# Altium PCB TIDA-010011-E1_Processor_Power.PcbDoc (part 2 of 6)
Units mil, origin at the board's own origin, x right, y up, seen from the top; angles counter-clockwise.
Board outline 4921.26 x 4921.26 mil, 4 copper layers (Top Layer, Gnd layer, Gnd/Pwr layer, Bottom Layer), stack 62.634 mil thick; 631 components, 254 nets, 1751 pads, 757 vias.
Unrouted connection lines stored in the file: 1.
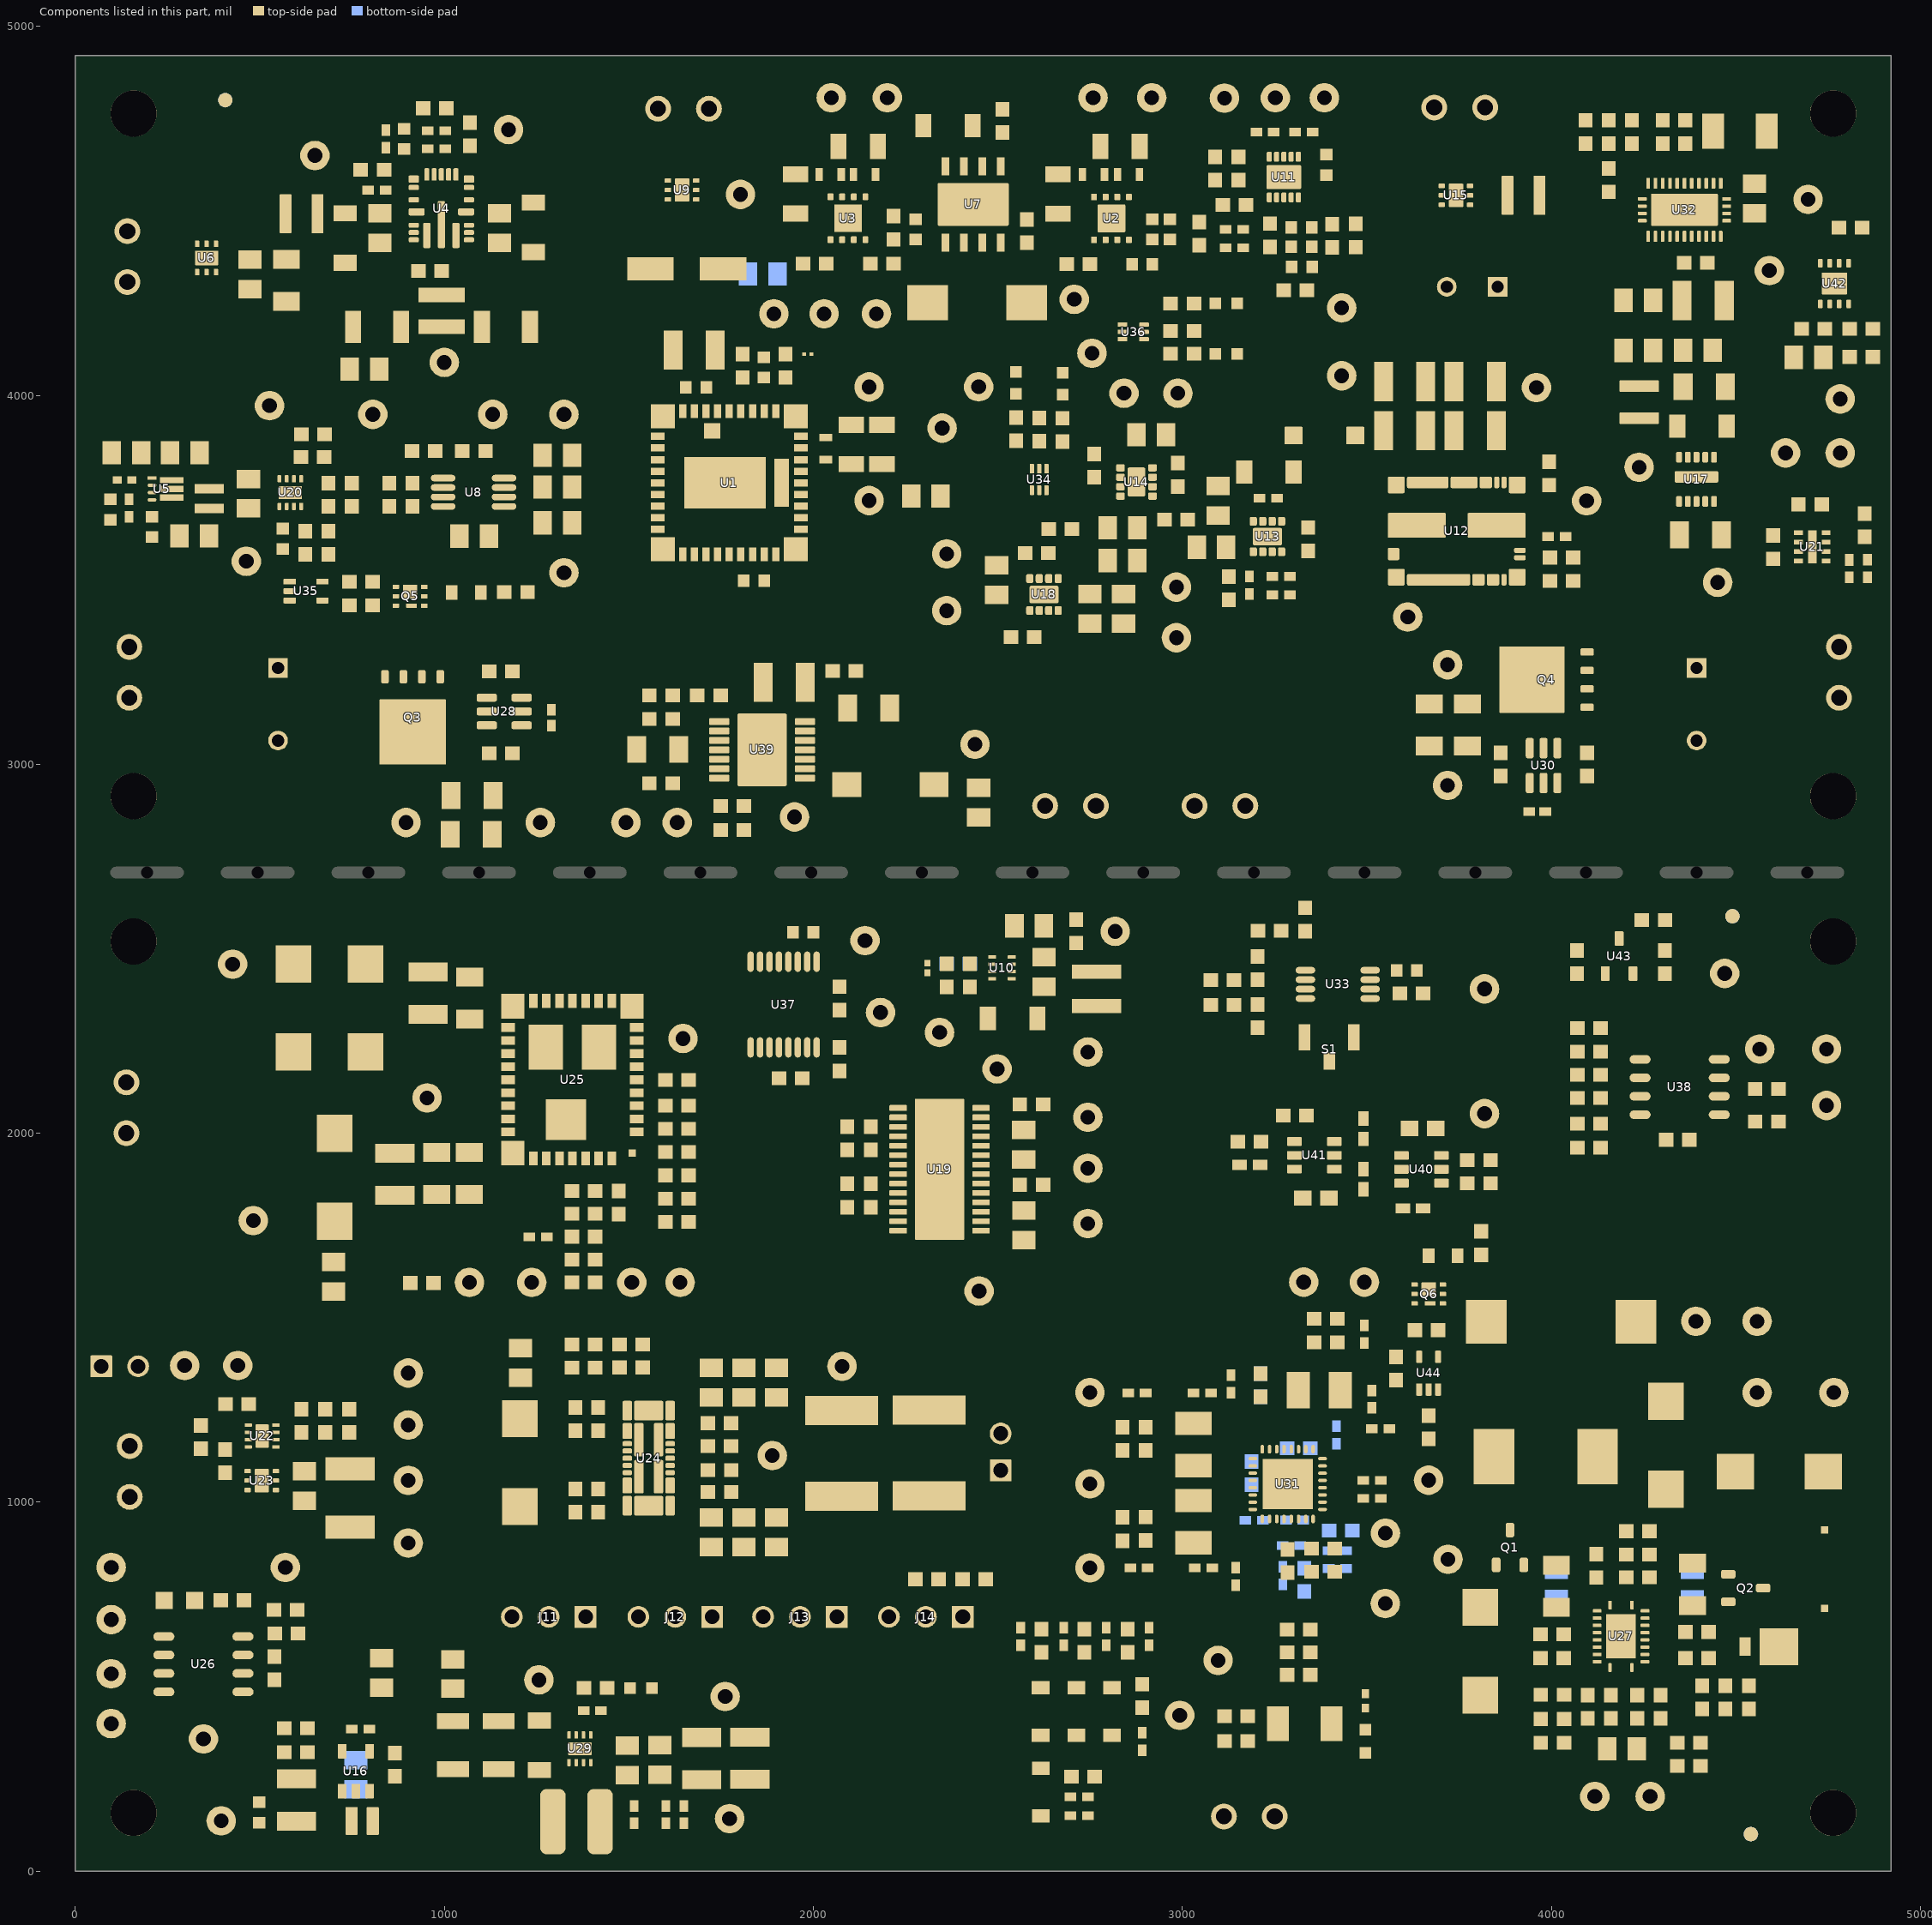
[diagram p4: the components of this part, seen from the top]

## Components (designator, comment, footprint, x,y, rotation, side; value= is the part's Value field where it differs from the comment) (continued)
U17 "LMZM23601V5SILR" SIL0010A 4393.62,3772.22 r270 top
U18 "TPS82085SILR" SIL0008C_SMD 2625.13,3459.94 r90 top
U19 "TPS767D318PWPR" PWP0028D_L 2342,1902 r0 top
U20 "INA381A1DSG" DSG0008A 582.28,3736.26 r90 top
U21 "LMZ10501SIL" SIL0008A 4707.4,3589.2 r180 top
U22 "TPS259531DSGR" DSG0008A 506,1179 r0 top
U23 "TVS1400DRVR" DRV0006A 505,1058.28 r0 top
U24 "TPSM82480MOPR" MOP0024A 1553.73,1118.92 r270 top
U25 "LMZ30604RKGR" RKG0039A 1347.16,2144.93 r180 top
U26 "TPS3705-33DR" D0008A_N 346.81,560.48 r180 top
U27 "TPS75003RHLR" RHL0020A 4189.04,636.15 r180 top
U28 "LM5050-2" tsop-6 1162,3143 r180 top
U29 "TPS62067DSGR" DSG0008A 1367.16,331.4 r90 top
U30 "LM5050-2" tsop-6 3979,2996.43 r90 top
U31 "TPS650250RHBR" RHB0032E 3285.49,1048.84 r0 top
U32 "LM73605RNPR" RNP0030A 4360.91,4502.84 r270 top
U33 "TPS386596L33DGKT" DGK0008A_N 3421.3,2403.31 r0 top
U34 "SN74LVC2G34DRLR" DRL0006A 2612,3772 r90 top
U35 "SN74LVC1G14DCKR" DCK0005A_N 625,3469.26 r0 top
U36 "SN74LVC2G34DRLR" DRL0006A 2867,4171.72 r0 top
U37 "INA250A3PWR" PW0016A_N 1919.44,2348.61 r90 top
U38 "TMP75BIDR" D0008A_N 4348,2125 r180 top
U39 "TPS54325PWPR" PWP0014E_N 1861,3039 r0 top
U40 "TPS27081ADDCR" DDC0006A_N 3648,1902 r180 top
U41 "TPS3808G01DBVR" DBV0006A_N 3358,1940 r180 top
U42 "TPS7A8001ADRBR" DRB0008A 4767.55,4302.92 r90 top
U43 "TMP235DBZ" DBZ0003A_N 4184,2480 r90 top
U44 "SN74LVC1G17DCKR" DCK0005A_N 3667.59,1349.29 r90 top
ZZ1 "This Assembly Note is for PCB labels only" AssemblyNoteLabel 206.81,5575 r0 top
ZZ2 "These assemblies are ESD sensitive, ESD precautions shall be observed." AssemblyNote 206.81,5466.11 r0 top
ZZ3 "These assemblies must be clean and free from flux and all contaminants. Use of no clean flux is not acceptable." AssemblyNote 206.81,5377.56 r0 top
ZZ4 "These assemblies must comply with workmanship standards IPC-A-610 Class 2, unless otherwise specified." AssemblyNote 206.81,5289 r0 top

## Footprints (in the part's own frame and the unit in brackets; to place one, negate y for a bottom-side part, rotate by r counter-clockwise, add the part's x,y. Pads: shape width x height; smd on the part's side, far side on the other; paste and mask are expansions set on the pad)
0201 [mm] "Data from Kemet datasheet CC101_COM dated 7/28/11"
  rect 0.46x0.42 smd mask+0.048: 1(-0.33,0) 2(0.33,0)
  body extent -0.31,-0.16 0.31,0.16, height 0.26
0402#1 [mm] "0402 from SM-752 data"
  rect 0.8x0.6 smd: 1(-0.6,0) 2(0.6,0)
  silkscreen extent -1.22,-0.52 1.22,0.52, body extent -0.55,-0.3 0.55,0.3, height 0.6
0402#2 [mm] "0402 from SM-752 data"
  rect 0.8x0.6 smd: 1(-0.575,-0.013) 2(0.625,-0.013)
  silkscreen extent -1.19,-0.53 1.24,0.51, body extent -0.52,-0.31 0.57,0.29, height 0.6
0402L [mm] "0402 from SM-752 data"
  rect 0.6x0.5 smd: 1(-0.5,0) 2(0.5,0)
  body extent -0.55,-0.3 0.55,0.3, height 0.6
0402M [mm] "0402 from SM-752 data"
  rect 1x0.7 smd: 1(-0.7,0) 2(0.7,0)
  silkscreen extent -1.5,-0.64 1.51,0.65, body extent -0.55,-0.3 0.55,0.3, height 0.6
0603#1 [mm] "0603 from SM-752 data"
  rect 1x0.95 smd: 1(-0.8,0) 2(0.8,0)
  silkscreen extent -1.52,-0.69 1.52,0.69, body extent -0.87,-0.47 0.87,0.47, height 1
0603#2 [mm] "0603 from SM-752 data"
  rect 1x0.95 smd: 1(-0.866,0) 2(0.734,0)
  silkscreen extent -1.52,-0.69 1.52,0.69, body extent -0.87,-0.47 0.87,0.47, height 1
0603L [mm] "0603 from SM-752 data"
  rect 0.8x0.85 smd: 1(-0.7,0) 2(0.7,0)
  silkscreen extent -0.07,-0.33 0.07,0.33, body extent -0.87,-0.47 0.87,0.47, height 1
0603M [mm] "0603 from SM-752 data"
  rect 1.2x1.05 smd: 1(-0.9,0) 2(0.9,0)
  silkscreen extent -1.82,-0.84 1.82,0.84, body extent -0.87,-0.47 0.87,0.47, height 1
0603S [mil]
  rect 20x35 smd: 1(-30,0) 2(30,0)
  silkscreen extent -10,-17 10,17, body extent -34,-19 34,19, height 39
0805_HV [mil] "0805 with 30mil clearance between pads"
  rect 50x63 smd: 1(-40,0) 2(40,0)
  silkscreen extent -74,-40 74,40, body extent -43,-29 43,29, height 57
1206 [mm] "1206 from SM-752 data"
  rect 1.3x1.85 smd: 1(-1.45,0) 2(1.45,0)
  silkscreen extent -2.4,-1.21 2.4,1.21, body extent -1.7,-0.9 1.7,0.9, height 1.35
1206_180 [mm] "1206_180"
  rect 1.1x1.6 smd: 1(-1.7,0) 2(1.7,0)
  silkscreen extent -0.9,-1 0.9,1, body extent -1.75,-0.95 1.75,0.95, height 1.8
1206_190 [mm] "1206_190"
  rect 1.1x1.6 smd: 1(-1.7,0) 2(1.7,0)
  silkscreen extent -0.9,-1 0.9,1, body extent -1.75,-0.95 1.75,0.95, height 1.9
1206L [mm] "1206 from SM-752 data"
  rect 1.1x1.75 smd: 1(-1.35,0) 2(1.35,0)
  silkscreen extent -0.4,-0.77 0.4,0.77, body extent -1.7,-0.9 1.7,0.9, height 1.35
1210 [mm] "1210 from SM-752 data"
  rect 1.3x2.7 smd: 1(-1.45,0) 2(1.45,0)
  silkscreen extent -2.32,-1.57 2.32,1.57, body extent -1.7,-1.35 1.7,1.35, height 1.35
1210_270 [mm] "1210"
  rect 1.3x2.7 smd: 1(-1.45,0) 2(1.45,0)
  silkscreen extent -2.32,-1.57 2.32,1.57, body extent -1.7,-1.35 1.7,1.35, height 2.7
1210_280 [mm] "SMD, 2-Leads, Body 3.6x2.8mm, Height 2.8mm"
  rect 1.1x2.2 smd: 1(-1.65,0) 2(1.65,0)
  silkscreen extent -0.84,-1.4 0.84,1.4, body extent -1.8,-1.4 1.8,1.4, height 2.8
1806_HighSpeed [mm] "Wurth recommended land pattern"
  rrect8% 1.25x1.2 smd: 1(-2.125,0) 2(2.125,0)
  silkscreen extent -1.5,-1 1.5,1, body extent -2.25,-0.8 2.25,0.8, height 1.61
1812_280 [mm] "1812"
  rect 1.6x3.4 smd: 1(-2,0) 2(2,0)
  silkscreen extent -0.8,-1.6 0.8,1.6, body extent -2.4,-1.7 2.4,1.7, height 2.8
7343-20 [mm] "Medium density IPC, based on Kemet case V from T495 datasheet"
  rect 2.55x2.45 smd: 1(-3.025,0) 2(3.025,0)
  silkscreen extent -4.56,-2.3 3.8,2.3, body extent -3.8,-2.3 3.8,2.3, height 2
7343-30 [mm] "Medium Density based on Kemet T495 dimensions"
  rect 2.55x2.45 smd: 1(-3.025,0) 2(3.025,0)
  silkscreen extent -3.8,-2.25 3.8,2.25, body extent -3.8,-2.3 3.8,2.3, height 3.1
7343-43 [mm] "Medium density IPC based on Kemet T495 series"
  rect 2.55x2.45 smd: 1(-3.025,0) 2(3.025,0)
  silkscreen extent -4.56,-2.3 3.8,2.3, body extent -3.8,-2.3 3.8,2.3, height 4.3
AssemblyNote [mil] "Assembly Note"
AssemblyNoteLabel [mil] "Assembly Note for PCB Labels"
B_F_PMSSS4400025PH [mil] "MACHINE SCREW PAN PHILLIPS 4-40"
  round 125 hole 125 unplated mask+5: 1(0,0)
  body extent -109,-109 110,110, height 79
Chemi-Con_1000x2000 [mm] "TH, 2-Leads, Body 10x20mm, Pin Spacing 5mm"
  rect 1.35x1.35 hole 0.85: 1(-2.5,0)
  round 1.35 hole 0.85: 2(2.5,0)
  silkscreen extent -5.25,-5.25 5.25,5.25, body extent -5.25,-5.25 5.25,5.25, height 21.5
CKG57N [mm] "Chip Capacitor, Body 6.0x5.0x5.0mm,"
  rect 2x5 smd: 1(-2.95,0) 2(2.95,0)
  silkscreen extent -3.2,-2.8 3.2,2.8, body extent -3.3,-2.75 3.3,2.75, height 5.5
CONN_1751248 [mil] "Phoenix Contact"
  round 70 hole 43.31: 1(-68.9,0) 2(68.9,0)
  silkscreen extent -148,-142 148,146, body extent -148,-142 148,146, height 335
CONN_PEC02SAAN [mm] "SULLINS"
  rrect7% 1.5x1.5 hole 1.016: 1(-1.27,0)
  round 1.5 hole 1.016: 2(1.27,0)
  silkscreen extent -2.54,-1.52 2.54,1.27, body extent -2.54,-1.27 2.54,1.27, height 8.38
CONN_PEC03SAAN [mm] "SULLINS"
  rect 1.5x1.5 hole 1.016: 1(-2.54,0)
  round 1.5 hole 1.016: 2(0,0) 3(2.54,0)
  silkscreen extent -3.81,-2.06 3.81,1.27, body extent -3.84,-1.3 3.84,1.3, height 8.38
D0008A_N [mm] "SOIC, 8-Leads, Body 4.9x3.9mm, Pitch 1.27mm, IPC Medium Density"
  oval 1.45x0.6 smd: 1(-2.725,1.905) 2(-2.725,0.635) 3(-2.725,-0.635) 4(-2.725,-1.905) 5(2.725,-1.905) 6(2.725,-0.635) 7(2.725,0.635) 8(2.725,1.905)
  silkscreen extent -3.3,-2.5 0.9,2.5, body extent -3,-2.45 3,2.45, height 1.63
DBV0005A_N [mm] "SOT23, 5-Leads, Body 2.9x1.6mm, Pitch 0.95mm, Lead Span 2.8mm, IPC Medium Density"
  rrect17% 1x0.6 smd: 1(-1.375,0.95) 2(-1.375,0) 3(-1.375,-0.95) 4(1.375,-0.95) 5(1.375,0.95)
  silkscreen extent -0.25,-1.55 0.25,1.55, body extent -1.42,-1.46 1.42,1.46, height 1.09
DBV0006A_N [mm] "SOT23, 6-Leads, Body 2.9x1.6mm, Pitch 0.95mm, Lead Span 2.8mm, IPC Medium Density"
  rrect17% 1x0.6 smd: 1(-1.375,0.95) 2(-1.375,0) 3(-1.375,-0.95) 4(1.375,-0.95) 5(1.375,0) 6(1.375,0.95)
  silkscreen extent -1.68,-1.55 0.5,1.55, body extent -1.42,-1.46 1.42,1.46, height 1.12
DBZ0003A_N [mm] "SOT23, 3-Leads, Body 2.9x1.3mm, Pitch 0.95mm, Lead Span 2.4mm, IPC Medium Density"
  rrect17% 1x0.6 smd: 1(-1.2,0.95) 2(-1.2,-0.95) 3(1.2,0)
  silkscreen extent 0.2,-1.5 0.7,1.5, body extent -1.26,-1.46 1.26,1.46, height 0.98
DCK0005A_N [mm] "SOT353, 5-Leads, Body 2x1.3mm, Pitch 0.65mm, Lead Span 2.1mm, IPC Medium Density"
  rrect25% 0.85x0.4 smd: 1(-1.125,0.65) 2(-1.125,0) 3(-1.125,-0.65) 4(1.125,-0.65) 5(1.125,0.65)
  silkscreen extent -1.48,-1.02 0.55,1.1, body extent -1.14,-1 1.14,1, height 0.95
DDA0008A_L [mm] "SOIC, 8-Leads, Body 4.95x3.95mm, Pitch 1.27mm, Thermal Pad 2.29.2x2.29mm, IPC High Density"
  rrect18% 1.25x0.55 smd: 1(-2.625,1.905) 2(-2.625,0.635) 3(-2.625,-0.635) 4(-2.625,-1.905) 5(2.625,-1.905) 6(2.625,-0.635) 7(2.625,0.635) 8(2.625,1.905)
  rrect7% 2.95x4.9 smd paste-1.5 mask-1.5: 9(0,0)
  rrect4% 2.34x2.34 on Top Paste: 9(0,0)
  rrect4% 2.34x2.34 on Top Solder: 9(0,0)
  silkscreen extent -3.47,-2.47 1,2.5, body extent -2.98,-2.45 2.98,2.45, height 1.55
DDC0006A_N [mm]
  rrect17% 1x0.6 smd: 1(-1.375,0.95) 2(-1.375,0) 3(-1.375,-0.95) 4(1.375,-0.95) 5(1.375,0) 6(1.375,0.95)
  silkscreen extent -1.75,-1.52 0.7,1.53, body extent -1.43,-1.48 1.43,1.49, height 0.92
DGK0008A_N [mm] "TSOP, 8-Leads, Body 3x3mm, Pitch 0.65mm, IPC Medium Density"
  oval 1.35x0.45 smd: 1(-2.225,0.975) 2(-2.225,0.325) 3(-2.225,-0.325) 4(-2.225,-0.975) 5(2.225,-0.975) 6(2.225,-0.325) 7(2.225,0.325) 8(2.225,0.975)
  silkscreen extent -2.75,-1.55 0.95,1.55, body extent -2.45,-1.5 2.45,1.5, height 0.96
DLC0008A [mm] "VSON-HR-8"
  rrect40% 0.55x0.25 smd: 1(-0.675,0.75) 2(-0.675,0.25) 3(-0.675,-0.25) 4(-0.675,-0.75) 5(0.675,-0.75) 6(0.675,-0.25) 7(0.675,0.25) 8(0.675,0.75)
  silkscreen extent -0.75,-1.15 0.75,1.15, body extent -0.8,-1.05 0.8,1.05, height 1.02
DQJ0008A [mm] "SMD, 8-Leads, Body 5.75x4.9mm"
  rrect39% 0.91x0.51 smd paste-0.05 mask-0.05: 1(-2.795,1.905) 2(-2.795,0.635) 3(-2.795,-0.635) 4(-2.795,-1.905) 5(2.795,-1.905) 6(2.795,-0.635) 7(2.795,0.635) 8(2.795,1.905)
  rrect8% 1.58x1.25 on Top Paste: 9(-0.38,1.45) 9(-0.38,0) 9(-0.38,-1.45) 9(1.4,1.45) 9(1.4,0) 9(1.4,-1.45)
  rrect3% 3.48x4.47 on Top Solder: 9(0.55,0)
  rrect2% 4.49x4.57 smd paste-2.5 mask-2.5: 9(1.005,0)
  silkscreen extent -3,-2.6 3,2.6, body extent -3.13,-2.45 3.13,2.45, height 1.15
DQK0006C#1 [mm] "WSON"
  rrect12% 0.9x0.86 on Top Paste: 0(0,0.325)
  rrect34% 0.7x0.29 on Top Paste: 0(0.095,-0.65)
  rrect33% 0.45x0.3 smd: 1(-0.975,0.65) 2(-0.975,0) 3(-0.975,-0.65) 4(0.975,-0.65) 5(0.975,0) 6(0.975,0.65)
  rrect33% 0.75x0.3 smd paste-0.15: 7(0.095,-0.65)
  rrect11% 1x0.95 smd paste-0.5: 8(0,0.325)
  silkscreen extent -1.15,-1.15 1.15,1.15, body extent -1,-1 1,1, height 0.82
DQK0006C#2 [mm] "WSON"
  rrect50% 0.9x0.86 on Top Paste: 0(0,0.325)
  rrect50% 0.7x0.29 on Top Paste: 0(0.095,-0.65)
  rrect33% 0.45x0.3 smd: 1(-0.975,0.65) 2(-0.975,0) 3(-0.975,-0.65) 4(0.975,-0.65) 5(0.975,0) 6(0.975,0.65)
  rrect33% 0.75x0.3 smd paste-0.15: 7(0.095,-0.65)
  rrect11% 1x0.95 smd paste-0.5: 8(0,0.325)
  silkscreen extent -1.15,-1.15 1.15,1.15, body extent -1,-1 1,1, height 0.82
DRB0008A [mm] "SON, 8-Leads, Body 3x3mm, Pitch 0.65mm, Thermal Pad 1.75x1.5mm, TI Recommended"
  rrect33% 0.6x0.3 smd: 1(-1.4,0.975) 2(-1.4,0.325) 3(-1.4,-0.325) 4(-1.4,-0.975) 5(1.4,-0.975) 6(1.4,-0.325) 7(1.4,0.325) 8(1.4,0.975)
  rrect7% 1.5x1.75 smd paste-0.75: 9(0,0)
  Top Layer region: -0.465,-1.5 -0.465,-0.875 -0.75,-0.875 -0.75,0.875 -0.465,0.875 -0.465,1.5 -0.185,1.5 -0.185,0.875 0.185,0.875 0.185,1.5 0.465,1.5 0.465,0.875 0.75,0.875 0.75,-0.875 0.465,-0.875 0.465,-1.5 0.185,-1.5 0.185,-0.875 -0.185,-0.875 -0.185,-1.5
  silkscreen extent -1.73,-1.73 1.73,1.73, body extent -1.58,-1.57 1.57,1.58, height 1.01
DRC0010J [mm] "SON, 10-Leads, Body 3x3mm, Pitch 0.5mm, Thermal Pad 2.4x1.65mm, TI Recommended"
  rrect57% 0.7x0.35 smd paste-0.05 mask-0.05: 1(-1.4,1) 2(-1.4,0.5) 3(-1.4,0) 4(-1.4,-0.5) 5(-1.4,-1) 6(1.4,-1) 7(1.4,-0.5) 8(1.4,0) 9(1.4,0.5) 10(1.4,1)
  rrect40% 0.25x0.34 on Top Paste: 11(-0.25,1.53) 11(-0.25,-1.53) 11(0.25,1.53) 11(0.25,-1.53)
  rrect9% 1.5x1.06 on Top Paste: 11(0,0.63) 11(0,-0.63)
  rrect12% 1.65x2.4 smd paste-1 mask-2: 11(0,0)
  Top Layer region: -0.25,1.1 0.25,1.1 0.25,1.75 -0.25,1.75
  Top Layer region: -0.25,-1.75 0.25,-1.75 0.25,-1.1 -0.25,-1.1
  Top Layer region: -0.775,-1.25 -0.425,-1.25 -0.425,-1.65 -0.417,-1.688 -0.396,-1.721 -0.363,-1.742 -0.325,-1.75 -0.325,-1.75 -0.325,-1.75 -0.175,-1.75 -0.175,-1.75 -0.137,-1.742 -0.104,-1.721 -0.083,-1.688 -0.075,-1.65 -0.075,-1.65 -0.075,-1.25 0.075,-1.25 0.075,-1.65 0.083,-1.688 0.104,-1.721 0.137,-1.742 0.175,-1.75 0.175,-1.75 0.175,-1.75 0.325,-1.75 0.325,-1.75 0.363,-1.742 0.396,-1.721 0.417,-1.688 0.425,-1.65 0.425,-1.65 0.425,-1.25 0.775,-1.25 0.813,-1.242 0.846,-1.221 0.867,-1.188 0.875,-1.15 0.875,-1.15 0.875,1.15 0.867,1.188 0.846,1.221 0.813,1.242 0.775,1.25 0.775,1.25 0.425,1.25 0.425,1.65 0.417,1.688 0.396,1.721 0.363,1.742 0.325,1.75 0.325,1.75 0.175,1.75 0.137,1.742 0.104,1.721 0.083,1.688 0.075,1.65 0.075,1.65 0.075,1.25 -0.075,1.25 -0.075,1.65 -0.083,1.688 -0.104,1.721 -0.137,1.742 -0.175,1.75 -0.175,1.75 -0.325,1.75 -0.363,1.742 -0.396,1.721 -0.417,1.688 -0.425,1.65 -0.425,1.65 -0.425,1.25 -0.775,1.25 -0.813,1.242 -0.846,1.221 -0.867,1.188 -0.875,1.15 -0.875,1.15 -0.875,-1.15 -0.867,-1.188 -0.846,-1.221 -0.813,-1.242 -0.775,-1.25
  silkscreen extent -1.63,-1.63 1.63,1.63, body extent -1.5,-1.5 1.5,1.5, height 0.77
DRL0006A [mm] "SOTFL, 6-Flat Leads, Body 1.2x1.6x0.6mm, Pitch 0.5mm, TI recommended"
  rrect33% 0.67x0.3 smd: 1(-0.74,0.5) 2(-0.74,0) 3(-0.74,-0.5) 4(0.74,-0.5) 5(0.74,0) 6(0.74,0.5)
  silkscreen extent -0.9,-0.95 0.5,0.95, body extent -0.8,-0.8 0.8,0.8, height 0.61
DRV0006A [mm] "SON, 6-Leads, Body 2x2mm, Pitch 0.65mm, Thermal Pad 1.6x1mm, TI Recommended"
  rrect33% 0.45x0.3 smd: 1(-0.975,0.65) 2(-0.975,0) 3(-0.975,-0.65) 4(0.975,-0.65) 5(0.975,0) 6(0.975,0.65)
  rrect14% 1x0.7 on Top Paste: 7(0,0.45) 7(0,-0.45)
  rrect10% 1x1.6 smd paste-0.5: 7(0,0)
  silkscreen extent -1.05,-1.2 1.05,1.2, body extent -1.05,-1.05 1.05,1.05, height 0.81
DSG0008A [mm] "SON, 8-Leads, Body 2x2mm, Pitch 0.5mm, Thermal Pad 1.6x0.9mm, TI Recommended"
  rrect40% 0.5x0.25 smd: 1(-0.95,0.75) 2(-0.95,0.25) 3(-0.95,-0.25) 4(-0.95,-0.75) 5(0.95,-0.75) 6(0.95,-0.25) 7(0.95,0.25) 8(0.95,0.75)
  rrect14% 0.9x0.7 on Top Paste: 9(0,0.45) 9(0,-0.45)
  rrect11% 0.9x1.6 smd paste-0.45: 9(0,0)
  silkscreen extent -1.07,-1.15 1.07,1.15, body extent -1,-1 1,1, height 0.77
ESD_Overlay_Medium [mil]
  silkscreen extent -127,-109 125,110
FCC_disclaimer_stacked [mil]
Fiducial10-30 [mm]
  round 1 smd mask+1: 1(0,0)
  Top Layer keep-out circle w1.678: c0,0 r0.75
GX_2TERM [mm] "PANASONIC"
  rect 2.8x2.4 smd: 1(-3.4,0) 2(3.4,0)
  silkscreen extent -4.45,-2.4 3.8,2.4, body extent -3.75,-2.25 3.75,2.25, height 2.01
IND_WE-LHMI-4020 [mm] "WERTH"
  rect 1.5x2.4 smd: 1(-1.85,0) 2(1.85,0)
  silkscreen extent -2.2,-2.2 2.2,2.2, body extent -2.15,-2.15 2.15,2.15, height 2
Keystone5000 [mil] "For Keystone 500x miniature loop terminals"
  round 80 hole 40: 1(0,0)
  silkscreen extent -52,-52 52,52, body extent -49,-49 49,49, height 182
Keystone5001 [mil] "For Keystone 500x miniature loop terminals"
  round 80 hole 40: 1(0,0)
  silkscreen extent -52,-52 52,52, body extent -49,-49 49,49, height 182
Keystone5002 [mil] "For Keystone 500x miniature loop terminals"
  round 80 hole 40: 1(0,0)
  silkscreen extent -52,-52 52,52, body extent -49,-49 49,49, height 182
Keystone5003 [mil] "For Keystone 500x miniature loop terminals"
  round 80 hole 40: 1(0,0)
  silkscreen extent -52,-52 52,52, body extent -49,-49 49,49, height 182
Keystone_1902E [mil] "Hex Standoff, 4-40 threaded, nylon"
  round 1 on Mech4: 0(0,0)
  body extent -145,-126 146,126, height 1001
KZN_800x1500 [mm] "TH, 2-Leads, Dia 8mm, Pin Spacing 3.5mm"
  rect 1.35x1.35 hole 0.85: 1(-1.75,0)
  round 1.35 hole 0.85: 2(1.75,0)
  silkscreen extent -4.25,-4.25 4.25,4.25, body extent -4.22,-4.24 4.24,4.24, height 16.51
Label_650x200 [mil] "Thermal Transfer Label"
  round 1 on Mech13: 0(0,0)
  silkscreen extent -325,-100 325,100, body extent -325,-100 325,100, height 1
LED_LTST-C170_Red [mm] "LITE-ON"
  rect 1.2x1.2 smd: 1(-1.05,0) 2(1.05,0)
  silkscreen extent -1.6,-1 2.2,1, body extent -1.05,-0.67 1.05,0.67, height 1.1
LED_LTST-C190_G [mm] "Lite-On"
  rect 0.8x0.8 smd: 1(-0.75,0) 2(0.75,0)
  silkscreen extent 1.38,-0.5 1.75,0.5, body extent -0.85,-0.45 0.85,0.45, height 0.9
LG_M67K_Green [mm] "SMD, 2-Leads, Body 2x1.4mm, Pitch 2mm"
  rect 0.8x1 smd mask+0: 1(-1,0) 2(1,0)
  silkscreen extent -2.1,-1 1.05,1, body extent -1.05,-0.75 1.05,0.75, height 1.4
MOP0024A [mm] "QFM, 24-Leads, Body 3.6x7.9mm"
  rrect31% 1.35x0.65 smd paste-1 mask-0.05: 1(-3.275,1.475) 3(-3.275,-1.475) 11(3.275,-1.475) 13(3.275,1.475)
  rrect19% 1.17x0.52 on Top Paste: 1(3.275,1.475) 9(-3.275,1.475) 11(-3.275,-1.475) 19(3.275,-1.475)
  rrect15% 1.35x2 smd paste-1 mask-0.05: 2(-3.275,0) 12(3.275,0)
  rrect19% 0.95x0.52 on Top Paste: 2(1.875,1.475) 8(-1.875,1.475) 12(-1.875,-1.475) 18(1.875,-1.475)
  rrect31% 1.1x0.65 smd paste-1 mask-0.05: 4(-1.875,-1.475) 10(1.875,-1.475) 14(1.875,1.475) 20(-1.875,1.475)
  rrect57% 0.35x0.65 smd paste-0.05 mask-0.05: 5(-1,-1.475) 6(-0.5,-1.475) 7(0,-1.475) 8(0.5,-1.475) 9(1,-1.475) 15(1,1.475) 16(0.5,1.475) 17(0,1.475) 18(-0.5,1.475) 19(-1,1.475)
  rrect9% 1.17x1.7 on Top Paste: 10(-3.275,0) 20(3.275,0)
  rrect31% 2.3x0.65 smd paste-1 mask-0.05: 21(-1.275,0.675) 22(1.275,0.675) 23(1.275,-0.675) 24(-1.275,-0.675)
  rrect19% 0.98x0.52 on Top Paste: 21(0.685,0.675) 21(1.865,0.675) 22(-1.865,0.675) 22(-0.685,0.675) 23(-1.865,-0.675) 23(-0.685,-0.675) 24(0.685,-0.675) 24(1.865,-0.675)
  Top Layer region: -3.85,1 -3.888,0.992 -3.921,0.971 -3.942,0.938 -3.95,0.9 -3.95,0.9 -3.95,-1.7 -3.942,-1.738 -3.921,-1.771 -3.888,-1.792 -3.85,-1.8 -3.85,-1.8 -2.7,-1.8 -2.662,-1.792 -2.629,-1.771 -2.608,-1.738 -2.6,-1.7 -2.6,-1.7 -2.6,-0.025 -2.6,-0.025 -2.592,0.013 -2.571,0.046 -2.538,0.067 -2.5,0.075 -2.5,0.075 -0.225,0.075 -0.187,0.083 -0.154,0.104 -0.133,0.137 -0.125,0.175 -0.125,0.175 -0.125,0.9 -0.133,0.938 -0.154,0.971 -0.187,0.992 -0.225,1 -0.225,1 -1.225,1 -1.263,1.008 -1.296,1.029 -1.317,1.062 -1.325,1.1 -1.325,1.1 -1.325,1.7 -1.333,1.738 -1.354,1.771 -1.387,1.792 -1.425,1.8 -1.425,1.8 -2.325,1.8 -2.363,1.792 -2.396,1.771 -2.417,1.738 -2.425,1.7 -2.425,1.7 -2.425,1.1 -2.433,1.062 -2.454,1.029 -2.487,1.008 -2.525,1 -2.525,1
  Top Layer region: 3.85,1 3.888,0.992 3.921,0.971 3.942,0.938 3.95,0.9 3.95,0.9 3.95,-1.7 3.942,-1.738 3.921,-1.771 3.888,-1.792 3.85,-1.8 3.85,-1.8 2.7,-1.8 2.662,-1.792 2.629,-1.771 2.608,-1.738 2.6,-1.7 2.6,-1.7 2.6,-0.025 2.6,-0.025 2.592,0.013 2.571,0.046 2.538,0.067 2.5,0.075 2.5,0.075 0.225,0.075 0.187,0.083 0.154,0.104 0.133,0.137 0.125,0.175 0.125,0.175 0.125,0.9 0.133,0.938 0.154,0.971 0.187,0.992 0.225,1 0.225,1 1.225,1 1.263,1.008 1.296,1.029 1.317,1.062 1.325,1.1 1.325,1.1 1.325,1.7 1.333,1.738 1.354,1.771 1.387,1.792 1.425,1.8 1.425,1.8 2.325,1.8 2.363,1.792 2.396,1.771 2.417,1.738 2.425,1.7 2.425,1.7 2.425,1.1 2.433,1.062 2.454,1.029 2.487,1.008 2.525,1 2.525,1
  Top Layer region: -2.325,-1.8 -2.363,-1.792 -2.396,-1.771 -2.417,-1.738 -2.425,-1.7 -2.425,-1.7 -2.425,-0.175 -2.417,-0.137 -2.396,-0.104 -2.363,-0.083 -2.325,-0.075 -2.325,-0.075 -0.225,-0.075 -0.187,-0.083 -0.154,-0.104 -0.133,-0.137 -0.125,-0.175 -0.125,-0.175 -0.125,-0.9 -0.133,-0.938 -0.154,-0.971 -0.187,-0.992 -0.225,-1 -0.225,-1 -1.225,-1 -1.263,-1.008 -1.296,-1.029 -1.317,-1.062 -1.325,-1.1 -1.325,-1.1 -1.325,-1.7 -1.333,-1.738 -1.354,-1.771 -1.387,-1.792 -1.425,-1.8 -1.425,-1.8
  Top Layer region: 2.325,-1.8 2.363,-1.792 2.396,-1.771 2.417,-1.738 2.425,-1.7 2.425,-1.7 2.425,-0.175 2.417,-0.137 2.396,-0.104 2.363,-0.083 2.325,-0.075 2.325,-0.075 0.225,-0.075 0.187,-0.083 0.154,-0.104 0.133,-0.137 0.125,-0.175 0.125,-0.175 0.125,-0.9 0.133,-0.938 0.154,-0.971 0.187,-0.992 0.225,-1 0.225,-1 1.225,-1 1.263,-1.008 1.296,-1.029 1.317,-1.062 1.325,-1.1 1.325,-1.1 1.325,-1.7 1.333,-1.738 1.354,-1.771 1.387,-1.792 1.425,-1.8 1.425,-1.8
  silkscreen extent -4.15,-2 4.15,2, body extent -4,-1.85 4,1.85, height 1.55
MUA08A_N [mm] "TSOP, 8-Leads, Body 3x3mm, Pitch 0.65mm, IPC Medium Density"
  oval 1.7x0.45 smd: 1(-2.1,0.975) 2(-2.1,0.325) 3(-2.1,-0.325) 4(-2.1,-0.975) 5(2.1,-0.975) 6(2.1,-0.325) 7(2.1,0.325) 8(2.1,0.975)
  silkscreen extent -2.22,-1.55 0.85,1.87, body extent -1.6,-1.6 1.6,1.6, height 1.09
Net-Tie_10mil [mil] "10mil net tie, no solder mask opening, no solder paste"
  rect 10x10 smd paste-5 mask-5: 1(-10,0) 2(10,0)
  Top Layer region: -6,5 6,5 6,-5 -6,-5
NR3015 [mm] "SMD, 2-Leads, Body 3x3mm"
  rrect12% 0.8x2.7 smd: 1(-1.1,0) 2(1.1,0)
  silkscreen extent -0.3,-1.6 0.3,1.6, body extent -1.5,-1.5 1.5,1.5, height 1.5
Pb-Free_Overlay_Small [mil]
  silkscreen extent -46,-46 46,46
POWERMITE [mil] "On Semi recommended land pattern, 457-04.pdf Rev 04E dated 2008-11-26"
  rect 105x100 smd: 1(-46,0)
  rect 30x50 smd: 2(46,0)
  silkscreen extent -124,-63 61,63, body extent -94,-40 59,40, height 45
PW0016A_N [mm] "TSOP, 16-Leads, Body 5x4.4mm, Pitch 0.65mm, IPC Medium Density"
  oval 1.4x0.45 smd: 1(-2.95,2.275) 2(-2.95,1.625) 3(-2.95,0.975) 4(-2.95,0.325) 5(-2.95,-0.325) 6(-2.95,-0.975) 7(-2.95,-1.625) 8(-2.95,-2.275) 9(2.95,-2.275) 10(2.95,-1.625) 11(2.95,-0.975) 12(2.95,-0.325) 13(2.95,0.325) 14(2.95,0.975) 15(2.95,1.625) 16(2.95,2.275)
  silkscreen extent -3.5,-2.55 1.85,2.75, body extent -3.21,-2.5 3.21,2.5, height 1
PWP0014E_N [mm] "TSOP, 14-Leads, Body 5x4.4mm, Pitch 0.65mm, Thermal Pad 3x3 mm, IPC Medium Density"
  rrect22% 1.4x0.45 smd: 1(-2.95,1.95) 2(-2.95,1.3) 3(-2.95,0.65) 4(-2.95,0) 5(-2.95,-0.65) 6(-2.95,-1.3) 7(-2.95,-1.95) 8(2.95,-1.95) 9(2.95,-1.3) 10(2.95,-0.65) 11(2.95,0) 12(2.95,0.65) 13(2.95,1.3) 14(2.95,1.95)
  rrect6% 3.4x5 smd paste-2 mask-2: 15(0,0)
  rrect4% 2.46x2.31 on Top Paste: 15(0,0)
  rrect4% 2.46x2.31 on Top Solder: 15(0,0)
  silkscreen extent -3.47,-2.65 1.7,2.65, body extent -3.21,-2.5 3.21,2.5, height 1
PWP0028D_L [mm] "TSOP, 28-Leads, Body 9.7x4.4mm, Pitch 0.65mm, Exposed Pad, IPC High Density"
  rrect25% 1.2x0.4 smd: 1(-2.85,4.225) 2(-2.85,3.575) 3(-2.85,2.925) 4(-2.85,2.275) 5(-2.85,1.625) 6(-2.85,0.975) 7(-2.85,0.325) 8(-2.85,-0.325) 9(-2.85,-0.975) 10(-2.85,-1.625) 11(-2.85,-2.275) 12(-2.85,-2.925) 13(-2.85,-3.575) 14(-2.85,-4.225) 15(2.85,-4.225) 16(2.85,-3.575) 17(2.85,-2.925) 18(2.85,-2.275) 19(2.85,-1.625) 20(2.85,-0.975) 21(2.85,-0.325) 22(2.85,0.325) 23(2.85,0.975) 24(2.85,1.625) 25(2.85,2.275) 26(2.85,2.925) 27(2.85,3.575) 28(2.85,4.225)
  rrect3% 3.4x9.7 smd paste-1.7 mask-1.7: 29(0,0)
  rrect4% 2.4x6.46 on Top Paste: 29(0,0)
  rrect4% 2.4x6.46 on Top Solder: 29(0,0)
  silkscreen extent -3.5,-4.9 2,4.9, body extent -3.21,-4.85 3.21,4.85, height 1
RHB0032E [mm] "QFN, 32-Leads, Body 5x5mm, Pitch 0.5mm, Thermal Pad 3.45x3.45mm, TI Recommended"
  oval 0.6x0.24 smd: 1(-2.4,1.75) 2(-2.4,1.25) 3(-2.4,0.75) 4(-2.4,0.25) 5(-2.4,-0.25) 6(-2.4,-0.75) 7(-2.4,-1.25) 8(-2.4,-1.75) 17(2.4,-1.75) 18(2.4,-1.25) 19(2.4,-0.75) 20(2.4,-0.25) 21(2.4,0.25) 22(2.4,0.75) 23(2.4,1.25) 24(2.4,1.75)
  oval 0.24x0.6 smd: 9(-1.75,-2.4) 10(-1.25,-2.4) 11(-0.75,-2.4) 12(-0.25,-2.4) 13(0.25,-2.4) 14(0.75,-2.4) 15(1.25,-2.4) 16(1.75,-2.4) 25(1.75,2.4) 26(1.25,2.4) 27(0.75,2.4) 28(0.25,2.4) 29(-0.25,2.4) 30(-0.75,2.4) 31(-1.25,2.4) 32(-1.75,2.4)
  rect 3.45x3.45 smd paste-1.725: 33(0,0)
  silkscreen extent -2.72,-2.73 2.72,2.73, body extent -2.57,-2.57 2.58,2.58, height 1.01
RHL0020A [mm] "QFN, 20-Leads, Body 4.5x3.5mm, Pitch 0.5mm, Thermal Pad 3.05x2.05mm, TI Recommended"
  rrect42% 0.24x0.6 smd: 1(-0.75,2.15) 10(-0.75,-2.15) 11(0.75,-2.15) 20(0.75,2.15)
  rrect42% 0.6x0.24 smd: 2(-1.65,1.75) 3(-1.65,1.25) 4(-1.65,0.75) 5(-1.65,0.25) 6(-1.65,-0.25) 7(-1.65,-0.75) 8(-1.65,-1.25) 9(-1.65,-1.75) 12(1.65,-1.75) 13(1.65,-1.25) 14(1.65,-0.75) 15(1.65,-0.25) 16(1.65,0.25) 17(1.65,0.75) 18(1.65,1.25) 19(1.65,1.75)
  rrect12% 0.92x0.85 on Top Paste: 21(-0.56,1.05) 21(-0.56,0) 21(-0.56,-1.05) 21(0.56,1.05) 21(0.56,0) 21(0.56,-1.05)
  rrect5% 2.05x3.05 smd paste-2 mask+0: 21(0,0)
  Top Layer region: -0.975,-1.575 -0.425,-1.575 -0.425,-2.4 -0.417,-2.438 -0.396,-2.471 -0.363,-2.492 -0.325,-2.5 -0.325,-2.5 -0.225,-2.5 -0.187,-2.492 -0.154,-2.471 -0.133,-2.438 -0.125,-2.4 -0.125,-2.4 -0.125,-1.975 0.125,-1.975 0.125,-2.4 0.133,-2.438 0.154,-2.471 0.187,-2.492 0.225,-2.5 0.225,-2.5 0.325,-2.5 0.363,-2.492 0.396,-2.471 0.417,-2.438 0.425,-2.4 0.425,-2.4 0.425,-1.575 0.975,-1.575 1.013,-1.567 1.046,-1.546 1.067,-1.513 1.075,-1.475 1.075,-1.475 1.075,1.475 1.067,1.513 1.046,1.546 1.013,1.567 0.975,1.575 0.975,1.575 0.425,1.575 0.425,2.4 0.417,2.438 0.396,2.471 0.363,2.492 0.325,2.5 0.325,2.5 0.225,2.5 0.187,2.492 0.154,2.471 0.133,2.438 0.125,2.4 0.125,2.4 0.125,1.975 -0.125,1.975 -0.125,2.4 -0.133,2.438 -0.154,2.471 -0.187,2.492 -0.225,2.5 -0.225,2.5 -0.325,2.5 -0.363,2.492 -0.396,2.471 -0.417,2.438 -0.425,2.4 -0.425,2.4 -0.425,1.575 -0.975,1.575 -1.013,1.567 -1.046,1.546 -1.067,1.513 -1.075,1.475 -1.075,1.475 -1.075,-1.475 -1.067,-1.513 -1.046,-1.546 -1.013,-1.567 -0.975,-1.575
  silkscreen extent -1.98,-2.47 1.98,2.47, body extent -1.75,-2.25 1.75,2.25, height 1.01
RKG0039A [mm]
  rect 0.5x0.5 smd paste-0.25: 1(-4.1,5.05)
  rect 0.95x0.6 smd paste-0.025: 2(-4.425,3.6) 3(-4.425,2.7) 4(-4.425,1.8) 5(-4.425,0.9) 6(-4.425,0) 7(-4.425,-0.9) 8(-4.425,-1.8) 9(-4.425,-2.7) 10(-4.425,-3.6) 20(4.425,-3.6) 21(4.425,-2.7) 22(4.425,-1.8) 23(4.425,-0.9) 24(4.425,0) 25(4.425,0.9) 26(4.425,1.8) 27(4.425,2.7) 28(4.425,3.6)
  rect 1.6x1.7 smd paste-0.8: 11(-4.1,-5.05) 19(4.1,-5.05) 29(4.1,5.05)
  rect 0.6x0.95 smd paste-0.025: 12(-2.7,-5.425) 13(-1.8,-5.425) 14(-0.9,-5.425) 15(0,-5.425) 16(0.9,-5.425) 17(1.8,-5.425) 18(2.7,-5.425) 30(2.7,5.425) 31(1.8,5.425) 32(0.9,5.425) 33(0,5.425) 34(-0.9,5.425) 35(-1.8,5.425) 36(-2.7,5.425)
  rect 2.8x2.8 smd paste-1.387 mask-0.6: 37(0.45,2.75)
  rect 2.35x3.1 smd paste-1.537: 38(-1.83,-2.25) 39(1.84,-2.25)
  Top Layer region: -4.9,5.9 -3.3,5.9 -3.3,4.8 -3.9,4.2 -4.9,4.2
  silkscreen extent -5.15,-6.15 5.15,6.15, body extent -4.57,-5.57 4.57,5.57, height 2.91
RLR0018A [mm] "B2QFN, Body 7x9mm"
  rrect17% 1.15x1.17 smd paste-1.15 mask-1.15: 1(-3.175,4.165) 7(-3.175,-4.165) 10(3.175,-4.165) 15(3.175,4.165)
  rrect57% 0.8x0.35 smd paste-0.05 mask-0.05: 2(-3.35,3.25) 3(-3.35,2.75) 14(3.35,3.25)
  rrect25% 0.8x0.85 smd paste-0.4 mask-0.4: 4(-3.35,2) 12(3.35,1.5) 13(3.35,2.5)
  rrect25% 0.8x1.85 smd paste-0.4 mask-0.4: 5(-3.35,0.5)
  rrect25% 0.8x2.85 smd paste-0.4 mask-0.4: 6(-3.35,-2)
  rrect40% 0.25x0.5 on Top Solder: 8(-0.895,-4.45) 8(-0.395,-4.45) 8(0.105,-4.45) 18(-0.895,4.45) 18(-0.395,4.45) 18(0.105,4.45)
  rrect6% 1.6x3.48 on Top Solder: 8(-0.395,-2.521) 18(-0.395,2.519)
  rrect8% 1.7x4.005 smd paste-2 mask-2: 8(-0.395,-2.748) 18(-0.395,2.748)
  rrect25% 0.85x0.8 smd paste-0.4 mask-0.4: 9(1.58,-4.35)
  rrect25% 0.8x4.35 smd paste-0.4 mask-0.4: 11(3.35,-1.25)
  rrect57% 0.35x0.8 smd paste-0.05 mask-0.05: 16(1.83,4.35) 17(1.33,4.35)
  rrect40% 0.265x0.25 on Top Paste: ""(-3.568,3.75) ""(-3.568,-3.75) ""(3.568,3.75) ""(3.568,-3.75)
  rrect17% 0.585x0.61 on Top Paste: ""(-2.943,3.93) ""(-2.943,-3.93) ""(2.943,3.93) ""(2.943,-3.93)
  rrect40% 0.25x0.265 on Top Paste: ""(-2.775,4.568) ""(-2.775,-4.568) ""(-0.895,4.568) ""(-0.895,-4.568) ""(-0.395,4.568) ""(-0.395,-4.568) ""(0.105,4.568) ""(0.105,-4.568) ""(2.775,4.568) ""(2.775,-4.568)
  rrect15% 0.67x0.71 on Top Paste: ""(-0.83,3.9) ""(-0.83,2.99) ""(-0.83,2.08) ""(-0.83,1.17) ""(-0.83,-1.17) ""(-0.83,-2.08) ""(-0.83,-2.99) ""(-0.83,-3.9) ""(0.04,3.9) ""(0.04,2.99) ""(0.04,2.08) ""(0.04,1.17) ""(0.04,-1.17) ""(0.04,-2.08) ""(0.04,-2.99) ""(0.04,-3.9)
  Top Layer region: -3.7,-4.75 -3.719,-4.746 -3.735,-4.735 -3.746,-4.719 -3.75,-4.7 -3.75,-4.7 -3.75,-0.675 -3.742,-0.637 -3.721,-0.604 -3.688,-0.583 -3.65,-0.575 -3.65,-0.575 0.71,-0.575 0.729,-0.579 0.745,-0.59 0.756,-0.606 0.76,-0.625 0.76,-0.625 0.76,-4.7 0.756,-4.719 0.745,-4.735 0.729,-4.746 0.71,-4.75 0.71,-4.75
  Top Layer region: -3.65,-0.425 -3.688,-0.417 -3.721,-0.396 -3.742,-0.363 -3.75,-0.325 -3.75,-0.325 -3.75,1.325 -3.742,1.363 -3.721,1.396 -3.688,1.417 -3.65,1.425 -3.65,1.425 -2.5,1.425 -2.481,1.429 -2.465,1.44 -2.454,1.456 -2.45,1.475 -2.45,1.475 -2.45,4.7 -2.446,4.719 -2.435,4.735 -2.419,4.746 -2.4,4.75 -2.4,4.75 0.7,4.75 0.719,4.746 0.735,4.735 0.746,4.719 0.75,4.7 0.75,4.7 0.75,3.85 0.754,3.831 0.765,3.815 0.781,3.804 0.8,3.8 0.8,3.8 2.4,3.8 2.419,3.796 2.435,3.785 2.446,3.769 2.45,3.75 2.45,3.75 2.45,-3.75 2.446,-3.769 2.435,-3.785 2.419,-3.796 2.4,-3.8 2.4,-3.8 0.96,-3.8 0.941,-3.796 0.925,-3.785 0.914,-3.769 0.91,-3.75 0.91,-3.75 0.91,-0.475 0.906,-0.456 0.895,-0.44 0.879,-0.429 0.86,-0.425 0.86,-0.425
  silkscreen extent -4,-5 4,5, body extent -3.57,-4.57 3.57,4.57, height 4.1
RLT0007A [mm] "TI"
  rect 0.6x0.25 smd paste-0.2: 1(-0.9,0.75)
  oval 0.6x0.25 smd paste-0.2: 2(-0.9,0.25) 3(-0.9,-0.25) 4(-0.9,-0.75)
  rect 1.64x0.44 smd paste-0.22 mask-0.07: 5(0.45,-0.6) 6(0.45,0) 7(0.45,0.6)
  silkscreen extent -1.1,-1.15 1.1,1.15, body extent -1,-1 1,1, height 1
RNL0022A_NV [mm] "VQFN, 22 pin, 0.5 mm pitch"
  rrect25% 0.7x0.5 smd paste-0.05 mask-0.05: 1(-1.9,2) 17(1.9,2)
  rrect40% 0.7x0.35 smd paste-0.05 mask-0.05: 2(-1.9,1.425) 3(-1.9,0.575) 15(1.9,0.575) 16(1.9,1.425)
  rrect40% 1.1x0.5 smd paste-0.25 mask-0.05: 4(-1.7,-0.25) 14(1.7,-0.25)
  rrect25% 0.4x0.4 on Top Paste: 4A(-2,-0.25) 4B(-1.4,-0.25) 14A(1.4,-0.25) 14B(2,-0.25)
  rrect57% 0.7x0.35 smd paste-0.05 mask-0.05: 5(-1.9,-1.175) 6(-1.9,-1.675) 7(-1.9,-2.175) 11(1.9,-2.175) 12(1.9,-1.675) 13(1.9,-1.175)
  rrect40% 0.5x1.74 smd paste-0.25 mask-0.05: 8(-1,-1.875) 10(1,-1.875)
  rrect25% 0.4x0.66 on Top Paste: 8A(-1,-1.445) 8B(-1,-2.305) 10A(1,-1.445) 10B(1,-2.305)
  rrect40% 0.5x3.25 smd paste-0.25 mask-0.05: 9(0,-1.125)
  rrect25% 0.4x0.63 on Top Paste: 9A(0,0.12) 9B(0,-0.71) 9C(0,-1.54) 9D(0,-2.37)
  rrect40% 0.35x0.85 smd paste-0.05 mask-0.05: 18(1,2.325) 19(0.5,2.325) 20(0,2.325) 21(-0.5,2.325) 22(-1,2.325)
  silkscreen extent -2.15,-2.65 2.15,2.65, body extent -2,-2.5 2,2.5, height 0.9
RNP0030A [mm] "QFN, 30-Leads, Body 6x4mm, Pitch 0.5mm, Thermal Pad 4.6x2.2mm"
  rrect40% 0.75x0.25 smd: 1(-1.825,2.5) 2(-1.825,2) 3(-1.825,1.5) 4(-1.825,1) 5(-1.825,0.5) 6(-1.825,0) 7(-1.825,-0.5) 8(-1.825,-1) 9(-1.825,-1.5) 10(-1.825,-2) 11(-1.825,-2.5) 16(1.825,-2.5) 17(1.825,-2) 18(1.825,-1.5) 19(1.825,-1) 20(1.825,-0.5) 21(1.825,0) 22(1.825,0.5) 23(1.825,1) 24(1.825,1.5) 25(1.825,2) 26(1.825,2.5)
  rrect40% 0.25x0.6 smd: 12(-0.75,-2.9) 13(-0.25,-2.9) 14(0.25,-2.9) 15(0.75,-2.9) 27(0.75,2.9) 28(0.25,2.9) 29(-0.25,2.9) 30(-0.75,2.9)
  rrect5% 2.2x4.6 smd paste-3: 31(0,0)
  rrect10% 0.98x0.96 on Top Paste: 31A(-0.59,1.74) 31A(-0.59,0.58) 31A(-0.59,-0.58) 31A(-0.59,-1.74) 31A(0.59,1.74) 31A(0.59,0.58) 31A(0.59,-0.58) 31A(0.59,-1.74)
  silkscreen extent -2.17,-3.18 2.17,3.18, body extent -2,-3 2,3, height 0.77
RVQ0043A [mm]
  rect 1.65x1.65 smd paste-0.225: 1(-4.575,4.575) 11(-4.575,-4.575) 21(4.575,-4.575) 31(4.575,4.575)
  rect 0.95x0.5 smd paste-0.025: 2(-4.925,3.2) 3(-4.925,2.4) 4(-4.925,1.6) 5(-4.925,0.8) 6(-4.925,0) 7(-4.925,-0.8) 8(-4.925,-1.6) 9(-4.925,-2.4) 10(-4.925,-3.2) 22(4.925,-3.2) 23(4.925,-2.4) 24(4.925,-1.6) 25(4.925,-0.8) 26(4.925,0) 27(4.925,0.8) 28(4.925,1.6) 29(4.925,2.4) 30(4.925,3.2)
  rect 0.5x0.95 smd paste-0.025: 12(-3.2,-4.925) 13(-2.4,-4.925) 14(-1.6,-4.925) 15(-0.8,-4.925) 16(0,-4.925) 17(0.8,-4.925) 18(1.6,-4.925) 19(2.4,-4.925) 20(3.2,-4.925) 32(3.2,4.925) 33(2.4,4.925) 34(1.6,4.925) 35(0.8,4.925) 36(0,4.925) 37(-0.8,4.925) 38(-1.6,4.925) 39(-2.4,4.925) 40(-3.2,4.925)
  rect 3.55x5.6 smd paste-1.78 mask-2: 41(0,0.3)
  rect 1.05x1.12 smd paste-1 mask+0: 42(3.575,1.187)
  rect 3.3x1 smd paste-0.5 mask+0: 43(0,-3.6)
  Top Layer region: 1.6,-4.1 2.25,-4.1 2.25,-3.1 1.6,-3.1
  Top Layer region: -2.25,-4.1 -1.6,-4.1 -1.6,-3.1 -2.25,-3.1
  Top Layer region: 2.925,0.027 4.1,0.027 4.1,0.762 2.925,0.762
  Top Layer region: 2.45,0.027 3.08,0.027 3.08,1.812 2.45,1.812
  Top Layer region: 2.45,1.712 4.1,1.712 4.1,2.347 2.45,2.347
  silkscreen extent -5.65,-5.65 5.65,5.65, body extent -5.07,-5.07 5.07,5.07, height 4.41
SIL0008A [mm] "POS, 8-Leads, Body 2.5x3.0mm, Pitch 0.65mm, NSC Recommended"
  rect 0.6x0.3 smd mask+0.07: 1(-0.95,0.975) 2(-0.95,0.325) 3(-0.95,-0.325) 4(-0.95,-0.975) 5(0.95,-0.975) 6(0.95,-0.325) 7(0.95,0.325) 8(0.95,0.975)
  rect 0.6x2.25 smd paste-0.3 mask+0.07: 9(0,0)
  silkscreen extent -1.45,-1.7 1.45,1.7, body extent -1.3,-1.5 1.3,1.5, height 1.43
SIL0008C_SMD [mm] "Solder Mask Defined pads"
  rrect40% 0.6x0.5 smd paste-0.05 mask-0.05: 1(-1.1,0.975) 2(-1.1,0.325) 3(-1.1,-0.325) 4(-1.1,-0.975) 5(1.1,-0.975) 6(1.1,-0.325) 7(1.1,0.325) 8(1.1,0.975)
  rrect17% 1.2x2 smd paste-0.6 mask-0.05: 9(0,0)
  silkscreen extent -1.55,-1.65 1.55,1.65, body extent -1.4,-1.5 1.4,1.5, height 1.31
SIL0008D_SMD [mm] "SIP, 8-Leads, Body 2.8x3.0mm, Pitch 0.65mm, Thermal Pad 1.9x1.1mm"
  rrect12% 1.04x0.85 on Top Paste: 0(0,0.525) 0(0,-0.525)
  rrect40% 0.6x0.5 smd paste-0.05 mask-0.05: 1(-1.05,0.975) 2(-1.05,0.325) 3(-1.05,-0.325) 4(-1.05,-0.975) 5(1.05,-0.975) 6(1.05,-0.325) 7(1.05,0.325) 8(1.05,0.975)
  rrect17% 1.2x2 smd paste-0.6 mask-0.05: 9(0,0)
  silkscreen extent -1.53,-1.63 1.53,1.63, body extent -1.4,-1.5 1.4,1.5, height 1.53
SIL0008F [mm]
  rrect25% 0.45x0.4 smd: 1(-1.475,1.2) 2(-1.475,0.4) 3(-1.475,-0.4) 4(-1.475,-1.2) 5(1.475,-1.2) 6(1.475,-0.4) 7(1.475,0.4) 8(1.475,1.2)
  rrect5% 1.9x1.9 smd paste-0.95: 9(0,0)
  silkscreen extent -1.9,-1.9 1.9,1.9, body extent -1.76,-1.75 1.74,1.75, height 1.66
SIL0010A [mm] "MicoSiP, TI recommended land pattern"
  rrect50% 0.75x0.4 smd paste-0.05 mask-0.05: 1(-1.525,1.2) 2(-1.525,0.6) 3(-1.525,0) 4(-1.525,-0.6) 5(-1.525,-1.2) 6(1.525,-1.2) 7(1.525,-0.6) 8(1.525,0) 9(1.525,0.6) 10(1.525,1.2)
  rrect14% 0.7x0.833 on Top Paste: 11(-0.175,1.03) 11(-0.175,0) 11(-0.175,-1.03)
  rrect25% 0.8x3 smd paste-0.5 mask-0.05: 11(-0.175,0)
  silkscreen extent -1.9,-1.68 1.9,1.68, body extent -1.9,-1.5 1.9,1.5, height 1.49
SM_RADIAL_D8 [mm] "6.3 x 7.7mm:  Panasonic D8"
  rect 3.2x1.6 smd: 1(-2.5,0) 2(2.5,0)
  silkscreen extent -3.4,-3.4 3.4,3.4, body extent -3.4,-3.4 3.4,3.4, height 8.01
SMC [mil] "Molded Diode, 2-Leads, Body 6.9x5.8mm, IPC Medium Density, based on OnSemi component dimensions and land patterns"
  rect 110x150 smd: 1(-140.49,0) 2(140.49,0)
  silkscreen extent -221,-123 189,124, body extent -156,-116 156,116, height 91
SOD-123 [mm] "On Semi recommended land pattern"
  rect 0.915x1.22 smd: 1(-1.637,0) 2(1.637,0)
  silkscreen extent -2.74,-1.17 2.03,1.17, body extent -1.93,-0.9 1.93,0.9, height 1.35
SOD-523 [mm] "NXP Semiconductor recommended land pattern, nominal STEP model"
  rect 0.8x0.6 smd paste-0.05: 1(-0.55,0) 2(0.55,0)
  silkscreen extent -1.65,-0.66 1.2,0.66, body extent -0.8,-0.4 0.8,0.4, height 0.72
SOT-23 [mm] "SOT23, 3-Leads, Body 2.9x1.3mm, Pitch 0.95mm, Lead Span 2.5mm, IPC Medium Density"
  rrect50% 1x0.6 smd: 1(-1.2,0.95) 2(-1.2,-0.95) 3(1.2,0)
  silkscreen extent -1.63,-1.5 0.7,1.5, body extent -1.16,-1.45 1.21,1.45, height 1
SW_B3U-1100P [mm] "SMD, 3-Leads, Body 3x2.5mm"
  rect 0.8x1.8 smd: 1(-1.7,0) 2(1.7,0)
  rect 0.8x1.2 smd: 3(0,1.65)
  silkscreen extent -2.83,-1.25 1.5,1.25, body extent -2,-1.25 2,1.9, height 1.6
tsop-6 [mm] "TSOP, 6-Leads, Body 3.1x1.7mm (max), Pitch 0.95mm, IPC Medium Density"
  rrect50% 1.4x0.55 smd: 1(-1.2,0.95) 2(-1.2,0) 3(-1.2,-0.95) 4(1.2,-0.95) 5(1.2,0) 6(1.2,0.95)
  silkscreen extent -1.68,1.5 -1.48,1.7, body extent -1.37,-1.5 1.38,1.5, height 1.05
VLCF4020 [mm] "TDK"
  rect 1.6x2.5 smd: 1(-1.45,0) 2(1.45,0)
  Top Layer region: -0.65,-1.95 -1.55,-1.95 -2.25,-1.25 -2.25,-1.15 -0.65,-1.15
  Top Layer region: -0.65,1.95 -1.55,1.95 -2.25,1.25 -2.25,1.15 -0.65,1.15
  Top Layer region: 0.65,1.95 1.55,1.95 2.25,1.25 2.25,1.15 0.65,1.15
  Top Layer region: 0.65,-1.95 1.55,-1.95 2.25,-1.25 2.25,-1.15 0.65,-1.15
  silkscreen extent -0.4,-2.1 0.4,2.1, body extent -2.05,-2.05 2.05,2.05, height 2
VLS2012ET [mm] "TDK"
  rect 0.65x2 smd: 1(-0.675,0) 2(0.675,0)
  silkscreen extent -0.15,-1.15 0.15,1.15, body extent -1.05,-1.05 1.05,1.05, height 1.2
WE-MAPI_2010 [mm] "WURTH"
  rrect12% 0.85x1.9 smd: 1(-0.725,0) 2(0.725,0)
  silkscreen extent -0.1,-1.07 0.1,1.07, body extent -1.1,-0.9 1.1,0.9, height 1
WE-PD2-S [mm] "WURTH"
  rrect50% 1.75x4.5 smd: 1(-1.625,0) 2(1.625,0)
  Top Layer region: -1.375,-2.25 -0.75,-2.25 -0.75,2.25 -1.375,2.25
  Top Layer region: 1.375,2.25 0.75,2.25 0.75,-2.25 1.375,-2.25
  silkscreen extent -0.4,-2.1 0.4,2.12, body extent -2.25,-2 2.25,2, height 3.18
WE-PD4-L [mm] "Wurth Elektronick recommended land pattern"
  rect 2.8x3 smd: 1(-5.15,0) 2(5.15,0)
  silkscreen extent -6.91,-5.1 6.91,5.1, body extent -6.45,-5.1 6.45,5.1, height 5.3
WE-PD_7332_PlasticBase [mm] "SMD Inductor, 2-Leads, Body 7,3x7,3mm"
  rect 2x1.7 smd: 1(-3,0) 2(3,0)
  silkscreen extent -3.8,-3.8 3.8,3.8, body extent -3.65,-3.65 3.65,3.65, height 3.19
WE-TPC-L [mm] "Wurth Elektronik recommended land pattern, 2009-01-15"
  rect 0.5x0.5 smd: 1(-2.7,0) 2(2.7,0)
  Top Layer region: 0.95,3.15 0.95,3.15 0.95,1.987 1.228,1.838 1.563,1.563 1.838,1.228 2.042,0.846 2.168,0.431 2.211,0 2.168,-0.431 2.042,-0.846 1.838,-1.228 1.563,-1.563 1.228,-1.838 0.95,-1.987 0.95,-3.15 3.15,-3.15 3.15,-3.15 3.15,3.15 0.95,3.15
  Top Layer region: -0.95,3.15 -0.95,3.15 -0.95,1.987 -1.228,1.838 -1.563,1.563 -1.838,1.228 -2.042,0.846 -2.168,0.431 -2.211,0 -2.168,-0.431 -2.042,-0.846 -1.838,-1.228 -1.563,-1.563 -1.228,-1.838 -0.95,-1.987 -0.95,-3.15 -3.15,-3.15 -3.15,-3.15 -3.15,3.15 -0.95,3.15
  silkscreen extent -3.4,-3.4 3.4,3.4, body extent -3.05,-3.05 3.05,3.05, height 2
WE-TPC_2828 [mm] "WURTH"
  rect 1x3.2 smd: 1(-1.1,0) 2(1.1,0)
  body extent -1.5,-1.5 1.5,1.5, height 3
WL-SMCW_GREEN [mm] "WURTH"
  rect 0.8x0.8 smd: 1(-0.8,0) 2(0.8,0)
  silkscreen extent -1.9,-0.8 1.2,0.8, body extent -0.85,-0.45 0.85,0.45, height 0.8
XFL4015 [mm] "SMD, 2-Leads, Body 4x4mm"
  rect 0.98x3.4 smd: 1(-1.185,0) 2(1.185,0)
  silkscreen extent -2.15,-2.15 2.15,2.15, body extent -2.15,-2.15 2.15,2.15, height 1.6

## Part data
C1: "CAP, AL, 47 µF, 50 V, +/- 20%, 0.68 ohm, SMD", Cap_Case=D8, Manufacturer=Panasonic, Supplier Part Number 1=PCE3816CT-ND, Tolerance_%=20, Value1="0.68 ohm", Value2=50V, ValueDisplayed=47µF
C2 C161 C188: "CAP, CERM, 10 µF, 50 V, +/- 10%, X7R, 1210", Cap_Case=1210, Manufacturer=MuRata, Supplier Part Number 1=490-6544-1-ND, TempCo=X7R, Tolerance_%=10, Value1=Unknown, Value2=50V, ValueDisplayed=10µF
C3 C26 C29 C37 C38 C39 C43 C147 C155 C159 C191: "CAP, CERM, 0.1 µF, 50 V, +/- 10%, X7R, 0603", Cap_Case=0603, Manufacturer=MuRata, Supplier Part Number 1=490-1519-1-ND, TempCo=X7R, Tolerance_%=10, Value1=Unknown, Value2=50V, ValueDisplayed=0.1µF
C4 C8 C11 C13 C16 C84 C87 C192: "CAP, CERM, 2.2 µF, 10 V, +/- 10%, X7R, 0603", Cap_Case=0603, Manufacturer=MuRata, Supplier Part Number 1=490-4520-1-ND, TempCo=X7R, Tolerance_%=10, Value1="0.009 ohm", Value2=10V, ValueDisplayed=2.2µF
C5 C6 C7 C12: "CAP, CERM, 47 µF, 10 V, +/- 10%, X5R, 1206", Cap_Case=1206, Manufacturer=MuRata, Supplier Part Number 1=490-9673-1-ND, TempCo=X5R, Tolerance_%=10, Value1=Unknown, Value2=10V, ValueDisplayed=47µF
C9: "CAP, CERM, 16 pF, 50 V, +/- 5%, C0G/NP0, 0603", Cap_Case=0603, Manufacturer=MuRata, Supplier Part Number 1=490-1408-1-ND, TempCo=C0G/NP0, Tolerance_%=5, Value1=Unknown, Value2=50V, ValueDisplayed=16pF
C10 C15: "CAP, CERM, 22 µF, 10 V, +/- 10%, X7R, 1206", Cap_Case=1206, Manufacturer=MuRata, Supplier Part Number 1=490-5309-1-ND, TempCo=X7R, Tolerance_%=10, Value1=Unknown, Value2=10V, ValueDisplayed=22µF
C14: "CAP, CERM, 20 pF, 50 V, +/- 5%, C0G/NP0, 0603", Cap_Case=0603, Manufacturer=MuRata, Supplier Part Number 1=490-1410-1-ND, TempCo=C0G/NP0, Tolerance_%=5, Value1=Unknown, Value2=50V, ValueDisplayed=20pF
C17: "CAP, CERM, 0.47 µF, 25 V, +/- 10%, X7R, AEC-Q200 Grade 1, 0603", Cap_Case=0603, Manufacturer=MuRata, Supplier Part Number 1=490-4776-1-ND, TempCo=X7R, Tolerance_%=10, Value1=Unknown, Value2=25V, ValueDisplayed=0.47µF
C18 C22 C23 C56 C172: "CAP, CERM, 0.1 µF, 100 V, +/- 10%, X7R, 0805", Cap_Case=0805, Manufacturer=TDK, Supplier Part Number 1=445-1418-1-ND, TempCo=X7R, Tolerance_%=10, Value1="0.020726 ohm", Value2=100V, ValueDisplayed=0.1µF
C19 C57: "CAP, CERM, 4.7 µF, 35 V, +/- 10%, X7R, 1206", Cap_Case=1206, Manufacturer=TDK, Supplier Part Number 1=445-14805-1-ND, TempCo=X7R, Tolerance_%=10, Value1="0.003785 ohm", Value2=35V, ValueDisplayed=4.7µF
C20 C21: "CAP, CERM, 10 µF, 25 V, +/- 10%, X7R, 1206", Cap_Case=2220, Manufacturer=MuRata, Supplier Part Number 1=490-6518-2-ND, TempCo=X7R, Tolerance_%=10, Value1=Unknown, Value2=25V, ValueDisplayed=10µF
C24 C25: "CAP, CERM, 22 µF, 16 V, +/- 20%, X7R, AEC-Q200 Grade 1, 1210", Cap_Case=1210_280, Manufacturer=TDK, Supplier Part Number 1=445-5723-1-ND, TempCo=X7R, Tolerance_%=20, Value1="0.002582 ohm", Value2=16V, ValueDisplayed=22µF
C27 C28 C110: "CAP, CERM, 22 µF, 6.3 V,+/- 10%, X5R, 0805", Cap_Case=0805, Manufacturer="Taiyo Yuden", Supplier Part Number 1=587-1468-1-ND, TempCo=X5R, Tolerance_%=10, Value1="0.002 ohm", Value2=6.3V, ValueDisplayed=22µF
C30: "CAP, CERM, 100 pF, 50 V,+/- 5%, C0G/NP0, 0603", Cap_Case=0603, Manufacturer=AVX, Supplier Part Number 1=478-1175-1-ND, TempCo=C0G/NP0, Tolerance_%=5, Value1="0.119 ohm", Value2=50V, ValueDisplayed=100pF
C31: "CAP, CERM, 1 µF, 6.3 V, +/- 10%, X7R, 0603", Cap_Case=0603, Manufacturer="Samsung Electro-Mechanics", Supplier Part Number 1=1276-1024-2-ND, TempCo=X7R, Tolerance_%=10, Value1=Unknown, Value2=6.3V, ValueDisplayed=1µF
C32: "CAP, CERM, 0.1 µF, 10 V, +/- 10%, X7R, 0603", Cap_Case=0603, Manufacturer=AVX, Supplier Part Number 1=478-7939-1-ND, TempCo=X7R, Tolerance_%=10, Value1=Unknown, Value2=10V, ValueDisplayed=0.1µF
C33: "CAP, CERM, 0.047 µF, 50 V,+/- 10%, X7R, 0805", Cap_Case=0805, Manufacturer=AVX, Supplier Part Number 1=478-1391-1-ND, TempCo=X7R, Tolerance_%=10, Value1="0.035 ohm", Value2=50V, ValueDisplayed=0.047µF
C34 C35 C36 C40 C41 C62 C63 C70 C71 C73 C74 C75 C78 C80 C81 C82 C170 C171: "CAP, CERM, 10 µF, 25 V, +/- 20%, X5R, 0603", Cap_Case=0603, Manufacturer=TDK, Supplier Part Number 1=445-9015-1-ND, TempCo=X5R, Tolerance_%=20, Value1=Unknown, Value2=25V, ValueDisplayed=10µF
C42 C177: "CAP, CERM, 4.7 µF, 16 V, +/- 10%, X5R, 0603", Cap_Case=0603, Manufacturer=MuRata, Supplier Part Number 1=490-10481-1-ND, TempCo=X5R, Tolerance_%=10, Value1=Unknown, Value2=16V, ValueDisplayed=4.7µF
C44: "CAP, CERM, 1000 pF, 25 V,+/- 10%, C0G/NP0, 0603", Cap_Case=0603, Manufacturer=Kemet, Supplier Part Number 1=399-7833-1-ND, TempCo=C0G/NP0, Tolerance_%=10, Value1="0 ohm", Value2=25V, ValueDisplayed=1000pF
C45: "CAP, AL, 47 µF, 100 V, +/- 20%, 0.14 ohm, TH", Cap_Case=8x15mm, Manufacturer=Chemi-Con, Supplier Part Number 1=565-4133-ND, Tolerance_%=20, Value1="0.14 ohm", Value2=100V, ValueDisplayed=47µF
C46 C47: "CAP, CERM, 4.7 µF, 50 V,+/- 10%, X7R, 1210", Cap_Case=1210, Manufacturer=MuRata, Supplier Part Number 1=490-1864-1-ND, TempCo=X7R, Tolerance_%=10, Value1="0.002 ohm", Value2=50V, ValueDisplayed=4.7µF
C48 C49: "CAP, CERM, 22 µF, 25 V,+/- 10%, X7R, 1210", Cap_Case=1210, Manufacturer=MuRata, Supplier Part Number 1=490-5313-1-ND, TempCo=X7R, Tolerance_%=10, Value1="0.002334 ohm", Value2=25V, ValueDisplayed=22µF
C50: "CAP, CERM, 22 µF, 6.3 V, +/- 20%, X5R, 0805", Cap_Case=0805, Manufacturer="Taiyo Yuden", Supplier Part Number 1=587-1305-1-ND, TempCo=X5R, Tolerance_%=20, Value1=Unknown, Value2=6.3V, ValueDisplayed=22µF
C51 C59: "CAP, CERM, 22 µF, 6.3 V, +/- 10%, X5R, 0805", Cap_Case=0805, Manufacturer="Taiyo Yuden", Supplier Part Number 1=587-1468-1-ND, TempCo=X5R, Tolerance_%=10, Value1="0.002 ohm", Value2=6.3V, ValueDisplayed=22µF
C52 C61 C126: "CAP, CERM, 10 µF, 10 V, +/- 10%, X7R, 0805", Cap_Case=0805, Manufacturer=MuRata, Supplier Part Number 1=490-3905-1-ND, TempCo=X7R, Tolerance_%=10, Value1="0.003 ohm", Value2=10V, ValueDisplayed=10µF
C53: "CAP, CERM, 470 pF, 50 V, +/- 5%, C0G/NP0, 0402", Cap_Case=0402, Manufacturer=MuRata, Supplier Part Number 1=490-1297-1-ND, TempCo=C0G/NP0, Tolerance_%=5, Value1=Unknown, Value2=50V, ValueDisplayed=470pF
C54: "CAP, CERM, 10 µF, 25 V, +/- 20%, X7R, 1206_190", Cap_Case=1206, Manufacturer=TDK, Supplier Part Number 1=445-6812-1-ND, TempCo=X7R, Tolerance_%=20, Value1=Unknown, Value2=25V, ValueDisplayed=10µF
C55: "CAP, CERM, 3300 pF, 50 V, +/- 5%, C0G/NP0, 0603", Cap_Case=0603, Manufacturer=MuRata, Supplier Part Number 1=GRM1885C1H332JA01D-ND, TempCo=C0G/NP0, Tolerance_%=5, Value1=Unknown, Value2=50V, ValueDisplayed=3300pF
C58: "CAP, CERM, 10 µF, 50 V,+/- 10%, X7R, 1206", Cap_Case=1206, Manufacturer="Samsung Electro-Mechanics", Supplier Part Number 1=1276-6767-1-ND, TempCo=X7R, Tolerance_%=10, Value2=50V, ValueDisplayed=10µF
C60: "CAP, CERM, 47 µF, 16 V,+/- 15%, X5R, 1206", Cap_Case=1206, Manufacturer=TDK, Supplier Part Number 1=445-6003-1-ND, TempCo=X5R, Tolerance_%=15, Value2=16V, ValueDisplayed=47µF
C64: "CAP, CERM, 470 pF, 50 V,+/- 10%, X7R, 0603", Cap_Case=0603, Manufacturer=MuRata, Supplier Part Number 1=490-1489-1-ND, TempCo=X7R, Tolerance_%=10, Value2=50V, ValueDisplayed=470pF
C65 C187: "CAP, CERM, 1 µF, 25 V,+/- 10%, X5R, 0805", Cap_Case=0805, Manufacturer=AVX, Supplier Part Number 1=478-1409-1-ND, TempCo=X5R, Tolerance_%=10, Value1="0.012 ohm", Value2=25V, ValueDisplayed=1µF
C66: "CAP, CERM, 22 µF, 25 V,+/- 20%, X5R, 1812", Cap_Case=1812, Manufacturer=TDK, Supplier Part Number 1=445-1444-1-ND, TempCo=X5R, Tolerance_%=20, Value1="0.002434 ohm", Value2=25V, ValueDisplayed=22µF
